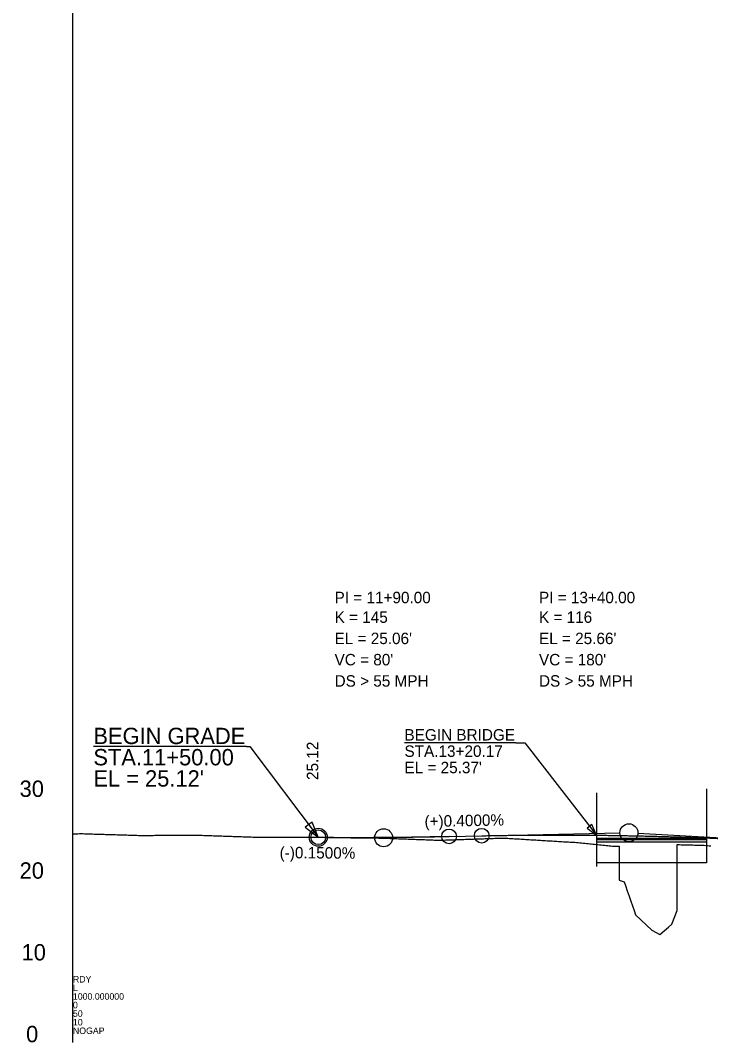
# Model space of a CAD drawing. Extents: x 2534543 to 2535313, y 713006 to 715506.
# Drawn here: x 2534543 to 2534965, y 714256 to 714881 of the extents above; entities that cross this region are included whole.
import ezdxf

# ---------------------------------------------------------------- set-up
doc = ezdxf.new("R2010")
doc.units = 0
for name, color, linetype in [('Exist Profile Cell', 7, 'Continuous'), ('Exist Vertical Profile Ground Line', 7, 'Continuous'), ('Exist Vertical Profile Vertical Axis Label', 7, 'Continuous'), ('Prop Vertical Profile Curve Label', 7, 'Continuous'), ('Prop Vertical Profile Grade', 7, 'Continuous'), ('Prop Vertical Profile Grade Label', 7, 'Continuous'), ('Prop VPI Label', 7, 'Continuous'), ('Scratch_Level_0', 7, 'Continuous'), ('Scratch_Level_2', 7, 'Continuous')]:
    doc.layers.add(name, color=color, linetype=linetype)

msp = doc.modelspace()

# ---------------------------------------------------------------- linework, layer by layer
at = {"layer": 'Exist Profile Cell'}
msp.add_line((2534574.89, 714255.81), (2534574.89, 715505.81), dxfattribs=at)
at = {"layer": 'Exist Vertical Profile Ground Line'}
for points in [[(2534574.89, 714383.39), (2534575.89, 714383.45), (2534576.89, 714383.52), (2534577.89, 714383.57), (2534578.89, 714383.63), (2534579.89, 714383.62), (2534580.89, 714383.59), (2534581.89, 714383.56), (2534582.89, 714383.53), (2534583.89, 714383.5), (2534584.89, 714383.47), (2534585.89, 714383.44), (2534586.89, 714383.41), (2534587.89, 714383.38), (2534588.89, 714383.35), (2534589.89, 714383.32), (2534590.89, 714383.29), (2534591.89, 714383.26), (2534592.89, 714383.23), (2534593.89, 714383.2), (2534594.89, 714383.17), (2534595.89, 714383.14), (2534596.89, 714383.11), (2534597.89, 714383.08), (2534598.89, 714383.05), (2534599.89, 714383.02), (2534600.89, 714382.99), (2534601.89, 714382.96), (2534602.89, 714382.93), (2534603.89, 714382.9), (2534604.89, 714382.87), (2534605.89, 714382.84), (2534606.89, 714382.81), (2534607.89, 714382.78), (2534608.89, 714382.74), (2534609.89, 714382.71), (2534610.89, 714382.68), (2534611.89, 714382.65), (2534612.89, 714382.62), (2534613.89, 714382.59), (2534614.89, 714382.56), (2534615.89, 714382.53), (2534616.89, 714382.53), (2534617.89, 714382.53), (2534618.89, 714382.54), (2534619.89, 714382.54), (2534620.89, 714382.55), (2534621.89, 714382.55), (2534622.89, 714382.56), (2534623.89, 714382.56), (2534624.89, 714382.57), (2534625.89, 714382.58), (2534626.89, 714382.58), (2534627.89, 714382.59), (2534628.89, 714382.59), (2534629.89, 714382.6), (2534630.89, 714382.6), (2534631.89, 714382.61), (2534632.89, 714382.61), (2534633.89, 714382.62), (2534634.89, 714382.63), (2534635.89, 714382.63), (2534636.89, 714382.64), (2534637.89, 714382.64), (2534638.89, 714382.65), (2534639.89, 714382.65), (2534640.89, 714382.66), (2534641.89, 714382.67), (2534642.89, 714382.67), (2534643.89, 714382.68), (2534644.89, 714382.68), (2534645.89, 714382.69), (2534646.89, 714382.69), (2534647.89, 714382.7), (2534648.89, 714382.7), (2534649.89, 714382.71), (2534650.89, 714382.69), (2534651.89, 714382.66), (2534652.89, 714382.62), (2534653.89, 714382.59), (2534654.89, 714382.55), (2534655.89, 714382.52), (2534656.89, 714382.49), (2534657.89, 714382.45), (2534658.89, 714382.43), (2534659.89, 714382.39), (2534660.89, 714382.36), (2534661.89, 714382.32), (2534662.89, 714382.29), (2534663.89, 714382.25), (2534664.89, 714382.22), (2534665.89, 714382.19), (2534666.89, 714382.15), (2534667.89, 714382.12), (2534668.89, 714382.08), (2534669.89, 714382.05), (2534670.89, 714382.01), (2534671.89, 714381.98), (2534672.89, 714381.95), (2534673.89, 714381.91), (2534674.89, 714381.88)], [(2534674.89, 714381.88), (2534675.89, 714381.84), (2534676.89, 714381.81), (2534677.89, 714381.77), (2534678.89, 714381.74), (2534679.89, 714381.71), (2534680.89, 714381.67), (2534681.89, 714381.64), (2534682.89, 714381.6), (2534683.89, 714381.57), (2534684.89, 714381.53), (2534685.89, 714381.5), (2534686.89, 714381.47), (2534687.89, 714381.45), (2534688.89, 714381.45), (2534689.89, 714381.45), (2534690.89, 714381.45), (2534691.89, 714381.44), (2534692.89, 714381.44), (2534693.89, 714381.44), (2534694.89, 714381.44), (2534695.89, 714381.44), (2534696.89, 714381.44), (2534697.89, 714381.44), (2534698.89, 714381.44), (2534699.89, 714381.43), (2534700.89, 714381.43), (2534701.89, 714381.43), (2534702.89, 714381.43), (2534703.89, 714381.43), (2534704.89, 714381.43), (2534705.89, 714381.43), (2534706.89, 714381.43), (2534707.89, 714381.42), (2534708.89, 714381.42), (2534709.89, 714381.42), (2534710.89, 714381.42), (2534711.89, 714381.42), (2534712.89, 714381.42), (2534713.89, 714381.42), (2534714.89, 714381.42), (2534715.89, 714381.41), (2534716.89, 714381.41), (2534717.89, 714381.41), (2534718.89, 714381.41), (2534719.89, 714381.41), (2534720.89, 714381.41), (2534721.89, 714381.41), (2534722.89, 714381.41), (2534723.89, 714381.4), (2534724.89, 714381.4), (2534725.89, 714381.39), (2534726.89, 714381.36), (2534727.89, 714381.35), (2534728.89, 714381.34), (2534729.89, 714381.32), (2534730.89, 714381.31), (2534731.89, 714381.3), (2534732.89, 714381.29), (2534733.89, 714381.27), (2534734.89, 714381.26), (2534735.89, 714381.25), (2534736.89, 714381.24), (2534737.89, 714381.22), (2534738.89, 714381.21), (2534739.89, 714381.2), (2534740.89, 714381.19), (2534741.89, 714381.17), (2534742.89, 714381.16), (2534743.89, 714381.15), (2534744.89, 714381.14), (2534745.89, 714381.13), (2534746.89, 714381.11), (2534747.89, 714381.1), (2534748.89, 714381.09), (2534749.89, 714381.08), (2534750.89, 714381.07), (2534751.89, 714381.05), (2534752.89, 714381.04), (2534753.89, 714381.03), (2534754.89, 714381.02), (2534755.89, 714381.01), (2534756.89, 714380.99), (2534757.89, 714380.98), (2534758.89, 714380.97), (2534759.89, 714380.96), (2534760.89, 714380.95), (2534761.89, 714380.93), (2534762.89, 714380.92), (2534763.89, 714380.89), (2534764.89, 714380.85), (2534765.89, 714380.81), (2534766.89, 714380.77), (2534767.89, 714380.74), (2534768.89, 714380.7), (2534769.89, 714380.66), (2534770.89, 714380.63), (2534771.89, 714380.59), (2534772.89, 714380.55), (2534773.89, 714380.51), (2534774.89, 714380.48)], [(2534774.89, 714380.48), (2534775.89, 714380.44), (2534776.89, 714380.4), (2534777.89, 714380.36), (2534778.89, 714380.33), (2534779.89, 714380.29), (2534780.89, 714380.25), (2534781.89, 714380.22), (2534782.89, 714380.18), (2534783.89, 714380.14), (2534784.89, 714380.1), (2534785.89, 714380.07), (2534786.89, 714380.03), (2534787.89, 714379.99), (2534788.89, 714379.95), (2534789.89, 714379.92), (2534790.89, 714379.88), (2534791.89, 714379.84), (2534792.89, 714379.8), (2534793.89, 714379.76), (2534794.89, 714379.72), (2534795.89, 714379.69), (2534796.89, 714379.65), (2534797.89, 714379.61), (2534798.89, 714379.6), (2534799.89, 714379.64), (2534800.89, 714379.67), (2534801.89, 714379.71), (2534802.89, 714379.74), (2534803.89, 714379.78), (2534804.89, 714379.81), (2534805.89, 714379.84), (2534806.89, 714379.88), (2534807.89, 714379.91), (2534808.89, 714379.94), (2534809.89, 714379.97), (2534810.89, 714380), (2534811.89, 714380.04), (2534812.89, 714380.07), (2534813.89, 714380.1), (2534814.89, 714380.14), (2534815.89, 714380.17), (2534816.89, 714380.2), (2534817.89, 714380.24), (2534818.89, 714380.27), (2534819.89, 714380.31), (2534820.89, 714380.34), (2534821.89, 714380.37), (2534822.89, 714380.41), (2534823.89, 714380.44), (2534824.89, 714380.47), (2534825.89, 714380.51), (2534826.89, 714380.54), (2534827.89, 714380.57), (2534828.89, 714380.61), (2534829.89, 714380.64), (2534830.89, 714380.67), (2534831.89, 714380.71), (2534832.89, 714380.74), (2534833.89, 714380.77), (2534834.89, 714380.81), (2534835.89, 714380.84), (2534836.89, 714380.88), (2534837.89, 714380.89), (2534838.89, 714380.88), (2534839.89, 714380.82), (2534840.89, 714380.76), (2534841.89, 714380.7), (2534842.89, 714380.64), (2534843.89, 714380.58), (2534844.89, 714380.52), (2534845.89, 714380.46), (2534846.89, 714380.4), (2534847.89, 714380.34), (2534848.89, 714380.27), (2534849.89, 714380.21), (2534850.89, 714380.15), (2534851.89, 714380.09), (2534852.89, 714380.03), (2534853.89, 714379.97), (2534854.89, 714379.91), (2534855.89, 714379.85), (2534856.89, 714379.79), (2534857.89, 714379.73), (2534858.89, 714379.67), (2534859.89, 714379.61), (2534860.89, 714379.55), (2534861.89, 714379.48), (2534862.89, 714379.42), (2534863.89, 714379.36), (2534864.89, 714379.3), (2534865.89, 714379.24), (2534866.89, 714379.18), (2534867.89, 714379.12), (2534868.89, 714379.06), (2534869.89, 714379), (2534870.89, 714378.94), (2534871.89, 714378.88), (2534872.89, 714378.82), (2534873.89, 714378.76), (2534874.89, 714378.69)], [(2534874.89, 714378.69), (2534875.89, 714378.63), (2534876.89, 714378.57), (2534877.89, 714378.51), (2534878.89, 714378.45), (2534879.89, 714378.39), (2534880.89, 714378.31), (2534881.89, 714378.3), (2534882.89, 714378.2), (2534883.89, 714378.1), (2534884.89, 714378), (2534885.89, 714377.9), (2534886.89, 714377.8), (2534887.89, 714377.7), (2534888.89, 714377.6), (2534889.89, 714377.49), (2534890.89, 714377.39), (2534891.89, 714377.29), (2534892.89, 714377.19), (2534893.89, 714377.09), (2534894.89, 714376.99), (2534895.89, 714376.89), (2534896.89, 714376.79), (2534897.89, 714376.69), (2534898.89, 714376.59), (2534899.89, 714376.49), (2534900.89, 714376.39), (2534901.89, 714376.29), (2534902.89, 714376.19), (2534903.89, 714376.08), (2534904.89, 714375.98), (2534905.89, 714375.88), (2534906.89, 714375.87), (2534907.89, 714375.91), (2534908.89, 714376)], [(2534908.89, 714376), (2534908.89, 714355.1), (2534910.77, 714354.54), (2534911.89, 714354.22), (2534912.74, 714351.81), (2534913.84, 714348.67), (2534914.98, 714345.42), (2534916.02, 714342.37), (2534916.98, 714339.56), (2534918.02, 714336.51), (2534918.89, 714333.95), (2534928.89, 714324.6), (2534933.89, 714321.92), (2534939.08, 714326.45), (2534941.13, 714328.24), (2534944.32, 714336.51), (2534944.32, 714350.89), (2534944.32, 714367.4), (2534944.32, 714376.91)], [(2534944.32, 714376.91), (2534945.89, 714376.88), (2534946.89, 714376.85), (2534947.89, 714376.83), (2534948.89, 714376.8), (2534949.89, 714376.77), (2534950.89, 714376.74), (2534951.89, 714376.72), (2534952.89, 714376.69), (2534953.89, 714376.66), (2534954.89, 714376.63), (2534955.89, 714376.61), (2534956.89, 714376.58), (2534957.89, 714376.55), (2534958.89, 714376.52), (2534959.89, 714376.5), (2534960.89, 714376.47), (2534961.89, 714376.44), (2534962.89, 714376.31), (2534963.89, 714376.18), (2534964.89, 714376.05)]]:
    msp.add_lwpolyline(points, dxfattribs=at)
at = {"layer": 'Prop Vertical Profile Curve Label'}
for centre in [(2534724.89, 714381.41), (2534804.89, 714381.91), (2534824.89, 714382.31)]:
    msp.add_circle(centre, 4.5, dxfattribs=at)
at = {"layer": 'Prop Vertical Profile Grade'}
msp.add_line((2534804.89, 714381.91), (2534824.89, 714382.31), dxfattribs=at)
for points in [[(2534724.89, 714381.41), (2534726.49, 714381.39), (2534728.09, 714381.38), (2534729.69, 714381.37), (2534731.29, 714381.36), (2534732.89, 714381.36), (2534734.49, 714381.35), (2534736.09, 714381.34), (2534737.69, 714381.34), (2534739.29, 714381.33), (2534740.89, 714381.33), (2534742.49, 714381.33), (2534744.09, 714381.32), (2534745.69, 714381.32), (2534747.29, 714381.32), (2534748.89, 714381.32), (2534750.49, 714381.33), (2534752.09, 714381.33), (2534753.69, 714381.33), (2534755.29, 714381.34), (2534756.89, 714381.34), (2534758.49, 714381.35), (2534760.09, 714381.35), (2534761.69, 714381.36), (2534763.29, 714381.37), (2534764.89, 714381.38), (2534766.49, 714381.39), (2534768.09, 714381.4), (2534769.69, 714381.41), (2534771.29, 714381.43), (2534772.89, 714381.44), (2534774.49, 714381.46), (2534776.09, 714381.47), (2534777.69, 714381.49), (2534779.29, 714381.51), (2534780.89, 714381.52), (2534782.49, 714381.54), (2534784.09, 714381.56), (2534785.69, 714381.58), (2534787.29, 714381.61), (2534788.89, 714381.63), (2534790.49, 714381.65), (2534792.09, 714381.68), (2534793.69, 714381.7), (2534795.29, 714381.73), (2534796.89, 714381.76), (2534798.49, 714381.78), (2534800.09, 714381.81), (2534801.69, 714381.84), (2534803.29, 714381.87), (2534804.89, 714381.91)], [(2534824.89, 714382.31), (2534828.49, 714382.37), (2534832.09, 714382.44), (2534835.69, 714382.5), (2534839.29, 714382.55), (2534842.89, 714382.6), (2534846.49, 714382.64), (2534850.09, 714382.67), (2534853.69, 714382.7), (2534857.29, 714382.73), (2534860.89, 714382.75), (2534864.49, 714382.76), (2534868.09, 714382.77), (2534871.69, 714382.77), (2534875.29, 714382.77), (2534878.89, 714382.76), (2534882.49, 714382.74), (2534886.09, 714382.72), (2534889.69, 714382.7), (2534893.29, 714382.67), (2534896.89, 714382.63), (2534900.49, 714382.59), (2534904.09, 714382.54), (2534907.69, 714382.49), (2534911.29, 714382.43), (2534914.89, 714382.36), (2534918.49, 714382.29), (2534922.09, 714382.22), (2534925.69, 714382.13), (2534929.29, 714382.05), (2534932.89, 714381.95), (2534936.49, 714381.86), (2534940.09, 714381.75), (2534943.69, 714381.64), (2534947.29, 714381.53), (2534950.89, 714381.41), (2534954.49, 714381.28), (2534958.09, 714381.15), (2534961.69, 714381.01), (2534965.29, 714380.87), (2534968.89, 714380.72), (2534972.49, 714380.57), (2534976.09, 714380.41), (2534979.69, 714380.24), (2534983.29, 714380.07), (2534986.89, 714379.9), (2534990.49, 714379.71), (2534994.09, 714379.53), (2534997.69, 714379.33), (2535001.29, 714379.13), (2535004.89, 714378.93)]]:
    msp.add_spline(points, degree=3, dxfattribs=at)
at = {"layer": 'Prop VPI Label'}
for p, q in [((2534804.89, 714381.91), (2534770.39, 714381.22)), ((2534824.89, 714382.31), (2534909.39, 714384)), ((2535004.89, 714378.93), (2534920.38, 714383.79)), ((2534724.89, 714381.41), (2534759.39, 714381.15))]:
    msp.add_line(p, q, dxfattribs=at)
for centre in [(2534914.89, 714384.11), (2534724.89, 714381.41), (2534764.89, 714381.11)]:
    msp.add_circle(centre, 5.5, dxfattribs=at)
at = {"layer": 'Scratch_Level_0'}
for p, q in [((2534894.96, 714408.64), (2534894.96, 714363.49)), ((2534962.31, 714410.91), (2534962.31, 714365.76)), ((2534962.31, 714380.56), (2534894.96, 714380.56)), ((2534962.31, 714379.72), (2534894.96, 714379.72)), ((2534962.31, 714378.47), (2534894.96, 714378.47)), ((2534962.31, 714365.76), (2534894.96, 714365.76))]:
    msp.add_line(p, q, dxfattribs=at)
at = {"layer": 'Scratch_Level_2'}
for p, q in [((2534845.78, 714439.04), (2534777.62, 714439.04)), ((2534680.99, 714436.85), (2534587.4, 714436.85))]:
    msp.add_line(p, q, dxfattribs=at)
for points in [[(2534845.78, 714439.04), (2534851.16, 714439.04), (2534894.96, 714382.65)], [(2534680.99, 714436.85), (2534683.04, 714436.85), (2534724.89, 714381.42)]]:
    msp.add_lwpolyline(points, dxfattribs=at)
for points in [[(2534717, 714387.57), (2534724.89, 714381.42), (2534721.14, 714390.69)], [(2534889.38, 714386.88), (2534894.96, 714382.65), (2534892.24, 714389.1)]]:
    msp.add_lwpolyline(points, close=True, dxfattribs=at)

# ---------------------------------------------------------------- texts
at = {"layer": 'Exist Profile Cell'}
for s, p in [('RDY', (2534574.89, 714292.56)), ('L', (2534574.89, 714287.31)), ('1000.000000', (2534574.89, 714282.06)), ('0', (2534574.89, 714276.81)), ('50', (2534574.89, 714271.56)), ('10', (2534574.89, 714266.31)), ('NOGAP', (2534574.89, 714261.06))]:
    msp.add_text(s, height=4, dxfattribs=at).set_placement(p)
at = {"layer": 'Exist Vertical Profile Vertical Axis Label'}
for s, p in [('30', (2534542.28, 714406.06)), ('20', (2534542.28, 714356.06)), ('10', (2534543.47, 714306.06)), ('0', (2534546.23, 714256.06))]:
    msp.add_text(s, height=10, dxfattribs=at).set_placement(p)
at = {"layer": 'Prop Vertical Profile Curve Label'}
for s, p in [('K = 145', (2534734.89, 714512.49)), ('K = 116', (2534859.89, 714512.49)), ("VC = 80'", (2534734.89, 714486.49)), ("VC = 180'", (2534859.89, 714486.49)), ('DS > 55 MPH', (2534734.89, 714473.49)), ('DS > 55 MPH', (2534859.89, 714473.49))]:
    msp.add_text(s, height=7, dxfattribs=at).set_placement(p)
at = {"layer": 'Prop Vertical Profile Grade Label'}
for s, rotation, p in [('(+)0.4000%', 1.14576, (2534789.94, 714387.61)), ('(-)0.1500%', 359.57029, (2534701.26, 714368.57))]:
    msp.add_text(s, height=7, rotation=rotation, dxfattribs=at).set_placement(p)
at = {"layer": 'Prop VPI Label'}
for s, p in [('PI = 11+90.00', (2534734.89, 714524.49)), ('PI = 13+40.00', (2534859.89, 714524.49)), ("EL = 25.06'", (2534734.89, 714499.49)), ("EL = 25.66'", (2534859.89, 714499.49))]:
    msp.add_text(s, height=7, dxfattribs=at).set_placement(p)
at = {"layer": 'Scratch_Level_0'}
msp.add_text('25.12', height=7, rotation=90, dxfattribs=at).set_placement((2534724.89, 714416.41))
at = {"layer": 'Scratch_Level_2'}
for s, height, p in [('BEGIN GRADE', 10, (2534587.4, 714438.35)), ('BEGIN BRIDGE', 7, (2534777.63, 714440.54)), ('STA.11+50.00', 10, (2534587.4, 714425.35)), ('STA.13+20.17', 7, (2534777.63, 714430.54)), ("EL = 25.37'", 7, (2534777.63, 714420.54)), ("EL = 25.12'", 10, (2534587.4, 714412.35))]:
    msp.add_text(s, height=height, rotation=0, dxfattribs=at).set_placement(p)

doc.saveas('drawing.dxf')
